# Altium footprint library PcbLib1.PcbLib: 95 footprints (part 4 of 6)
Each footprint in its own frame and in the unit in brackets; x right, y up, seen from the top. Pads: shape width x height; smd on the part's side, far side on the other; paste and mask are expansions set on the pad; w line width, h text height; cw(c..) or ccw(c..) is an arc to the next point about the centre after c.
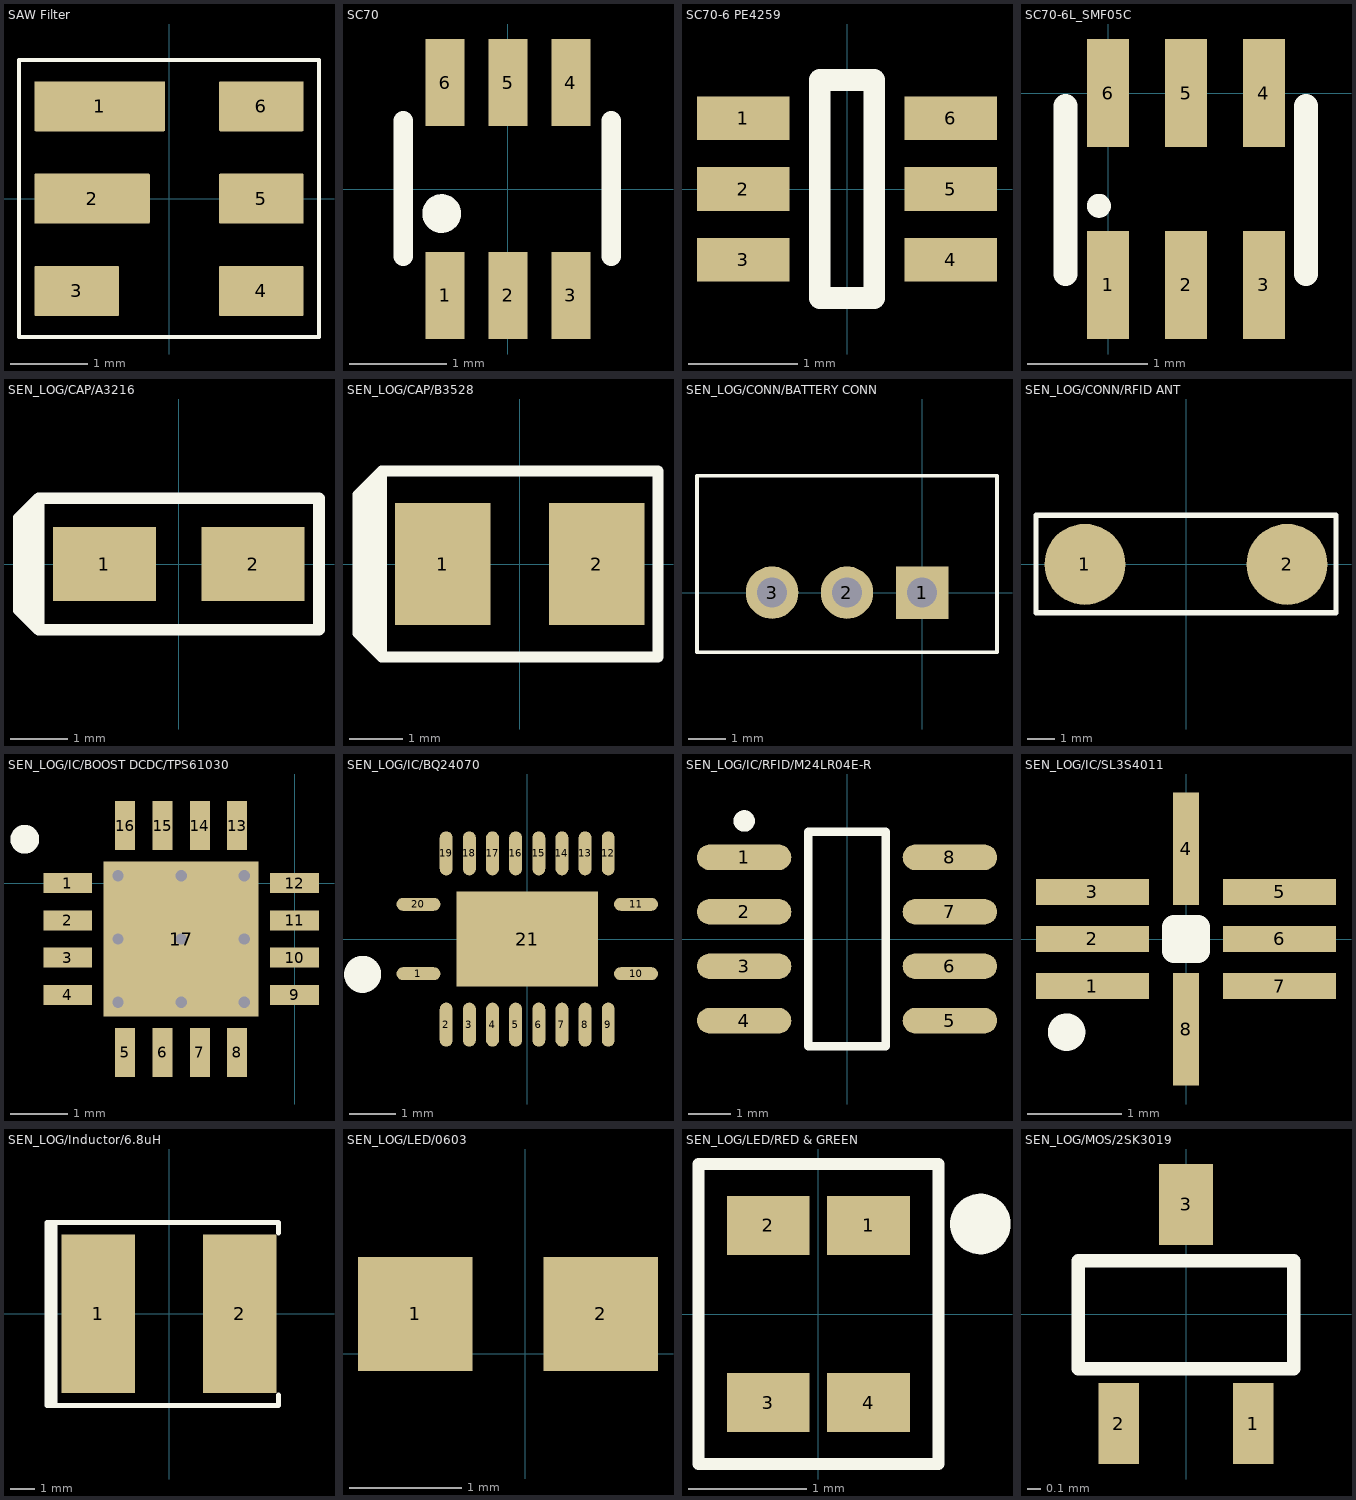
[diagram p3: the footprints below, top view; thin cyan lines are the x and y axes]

## SAW Filter [mm]
pads (6):
  rrect5% 1.7x0.65 smd mask+0.05: 1(-0.9,1.2)
  rrect5% 1.5x0.65 smd mask+0.05: 2(-1,0)
  rrect5% 1.1x0.65 smd mask+0.05: 3(-1.2,-1.2) 4(1.2,-1.2) 5(1.2,0) 6(1.2,1.2)
Top Overlay:
  lines w0.05: -1.95,-1.8 -1.95,1.8 1.95,1.8 1.95,-1.8 -1.95,-1.8

## SC70 [mm]
pads (6):
  rect 0.4x0.9 smd: 1(-0.65,-1.1) 2(0,-1.1) 3(0.65,-1.1) 4(0.65,1.1) 5(0,1.1) 6(-0.65,1.1)
Top Overlay:
  circle w0.2: c-0.686,-0.254 r0.1
  lines w0.2: -1.082,-0.694 -1.082,0.706 ; 1.068,-0.694 1.068,0.706

## SC70-6 PE4259 [mm]
pads (6):
  rect 0.85x0.4 smd mask+0.05: 1(-0.95,0.65) 2(-0.95,0) 3(-0.95,-0.65) 4(0.95,-0.65) 5(0.95,0) 6(0.95,0.65)
Top Overlay:
  lines w0.2: -0.25,-1 -0.25,1 0.25,1 0.25,-1 -0.25,-1

## SC70-6L_SMF05C [mm]
pads (6):
  rect 0.35x0.9 smd mask+0.05: 1(0,-1.6) 2(0.65,-1.6) 3(1.3,-1.6) 4(1.3,0) 5(0.65,0) 6(0,0)
Top Overlay:
  circle w0.1: c-0.076,-0.94 r0.05
  lines w0.2: -0.356,-1.506 -0.356,-0.106 ; 1.651,-1.506 1.651,-0.106

## SEN_LOG/CAP/A3216 [mm]
pads (2):
  rect 1.8x1.3 smd: 1(-1.3,0) 2(1.3,0)
Top Overlay:
  lines w0.203: -2.66,0.806 -2.794,0.806 ; -2.591,-0.914 -2.591,0.737 ; -2.54,-0.965 -2.54,0.965 ; -2.794,0.806 -2.45,1.15 ; -2.794,0.806 -2.794,-0.806 -2.45,-1.15 ; -2.45,-1.15 -2.45,1.15 ; -2.45,-1.15 2.45,-1.15 2.45,1.15 -2.45,1.15

## SEN_LOG/CAP/B3528 [mm]
pads (2):
  rect 1.8x2.3 smd: 1(-1.45,0) 2(1.45,0)
Top Overlay:
  lines w0.203: -2.87,-1.473 -2.87,1.422 ; -2.718,-1.499 -2.718,1.575 ; -2.6,-1.75 -3.048,-1.302 -3.048,1.302 -2.6,1.75 ; -2.6,-1.75 -2.6,1.75 ; -2.6,-1.75 2.6,-1.75 2.6,1.75 -2.6,1.75

## SEN_LOG/CONN/BATTERY CONN [mm]
pads (3):
  rect 1.4x1.4 hole 0.8: 1(0,0)
  round 1.4 hole 0.8: 2(-2,0) 3(-4,0)
Top Overlay:
  lines w0.1: -6,-1.588 2,-1.588 2,3.112 -6,3.112 -6,-1.588

## SEN_LOG/CONN/RFID ANT [mm]
pads (2):
  round 3 smd: 1(-3.75,0) 2(3.75,0)
Top Overlay:
  lines w0.203: -5.563,-1.803 5.563,-1.803 5.563,1.829 -5.563,1.829 -5.563,-1.803

## SEN_LOG/IC/BOOST DCDC/TPS61030 [mm]
pads (17):
  rect 0.85x0.35 smd paste-0.025 mask+0.07: 1(-3.95,0) 2(-3.95,-0.65) 3(-3.95,-1.3) 4(-3.95,-1.95) 9(0,-1.95) 10(0,-1.3) 11(0,-0.65) 12(0,0)
  rect 0.35x0.85 smd paste-0.025 mask+0.07: 5(-2.95,-2.95) 6(-2.3,-2.95) 7(-1.65,-2.95) 8(-1,-2.95) 13(-1,1) 14(-1.65,1) 15(-2.3,1) 16(-2.95,1)
  rect 2.7x2.7 smd mask+0.07: 17(-1.975,-0.975)
via -3.075,-2.075 diameter 0.4 hole 0.2
via -3.075,-0.975 diameter 0.4 hole 0.2
via -3.075,0.125 diameter 0.4 hole 0.2
via -1.975,0.125 diameter 0.4 hole 0.2
via -0.875,0.125 diameter 0.4 hole 0.2
via -0.875,-0.975 diameter 0.4 hole 0.2
via -0.875,-2.075 diameter 0.4 hole 0.2
via -1.975,-2.075 diameter 0.4 hole 0.2
via -1.975,-0.975 diameter 0.4 hole 0.2
Top Overlay:
  circle w0.3: c-4.699,0.762 r0.1

## SEN_LOG/IC/BQ24070 [mm]
pads (21):
  oval 0.95x0.28 smd: 1(-2.35,-0.75) 10(2.35,-0.75) 11(2.35,0.75) 20(-2.35,0.75)
  oval 0.28x0.95 smd: 2(-1.75,-1.85) 3(-1.25,-1.85) 4(-0.75,-1.85) 5(-0.25,-1.85) 6(0.25,-1.85) 7(0.75,-1.85) 8(1.25,-1.85) 9(1.75,-1.85) 12(1.75,1.85) 13(1.25,1.85) 14(0.75,1.85) 15(0.25,1.85) 16(-0.25,1.85) 17(-0.75,1.85) 18(-1.25,1.85) 19(-1.75,1.85)
  rect 3.05x2.05 smd: 21(0,0)
Top Overlay:
  circle w0.6: c-3.556,-0.762 r0.1

## SEN_LOG/IC/RFID/M24LR04E-R [mm]
pads (8):
  oval 2.2x0.6 smd: 1(-2.4,1.905) 2(-2.4,0.635) 3(-2.4,-0.635) 4(-2.4,-1.905) 5(2.4,-1.905) 6(2.4,-0.635) 7(2.4,0.635) 8(2.4,1.905)
Top Overlay:
  circle w0.25: c-2.4,2.755 r0.125
  lines w0.2: -0.9,-2.5 0.9,-2.5 0.9,2.5 -0.9,2.5 -0.9,-2.5

## SEN_LOG/IC/SL3S4011 [mm]
pads (8):
  rect 1.2x0.28 smd: 1(-0.995,-0.5) 5(0.995,0.5) 6(0.995,0) 7(0.995,-0.5)
  rect 1.2x0.28 smd mask+0.102: 2(-0.995,0) 3(-0.995,0.5)
  rect 0.28x1.2 smd: 4(0,0.96) 8(0,-0.96)
Top Overlay:
  circle w0.254: c-1.27,-0.991 r0.072
  lines w0.254: -0.127,-0.127 0.127,-0.127 0.127,0.127 -0.127,0.127 -0.127,-0.127

## SEN_LOG/Inductor/6.8uH [mm]
pads (2):
  rect 3x6.5 smd: 1(-2.9,0) 2(2.9,0)
Top Overlay:
  lines w0.2: -4.826,-3.766 -4.826,3.683 ; -4.674,-3.766 -4.674,3.683 ; 4.496,-3.334 4.496,-3.766 -5.004,-3.766 -5.004,3.734 4.496,3.734 4.496,3.302

## SEN_LOG/LED/0603 [mil]
pads (2):
  rect 40x40 smd: 1(-38.5,14) 2(26.5,14)

## SEN_LOG/LED/RED & GREEN [mm]
pads (4):
  rect 0.7x0.5 smd mask+0.06: 1(0.425,0.75) 2(-0.425,0.75) 3(-0.425,-0.75) 4(0.425,-0.75)
Top Overlay:
  circle w0.254: c1.372,0.762 r0.13
  lines w0.1: -1.016,-1.27 -1.016,1.27 1.016,1.27 1.016,-1.27 -1.016,-1.27

## SEN_LOG/MOS/2SK3019 [mm]
pads (3):
  rect 0.3x0.6 smd mask+0.07: 1(0.5,-0.813) 2(-0.5,-0.813)
  rect 0.4x0.6 smd mask+0.07: 3(0,0.813)
Top Overlay:
  lines w0.1: -0.8,-0.406 0.8,-0.406 0.8,0.394 -0.8,0.394 -0.8,-0.406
